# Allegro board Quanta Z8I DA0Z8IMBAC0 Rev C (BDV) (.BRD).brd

Outline 237.5 x 219.5 mm; copper layers: TOP, SGND, IN1, SVCC, IN2, IN3, SGND1, IN4, SGND2, BOTTOM. Coordinates in mm from the lower left corner of the outline.

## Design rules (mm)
constraint set DEFAULT: min track width 0.114
net group DFP-S4.5W4.5(3.5: nets PCIE_RCOMP PCIE_RCOMP_P
net group W12-T1234B: nets +3V_RTC +3VLCD_CON_R_C
net group W30-T1234B: nets +5V_KB CRT_VCC_R
net group W80-T1234B: nets +VIN_BLIGHT VCCPRIM_1P05
net group W99-T1234B: nets +VCC_CORE +VCCSA
net group DFP-S4(4: nets M_A_CLKN0 M_A_CLKN1 M_A_CLKP0 M_A_CLKP1 M_A_DQSN0 M_A_DQSN1 M_A_DQSN2 M_A_DQSN3 M_A_DQSN4 M_A_DQSN5 M_A_DQSN6 M_A_DQSN7 M_A_DQSP0 M_A_DQSP1 M_A_DQSP2 M_A_DQSP3 M_A_DQSP4 M_A_DQSP5 M_A_DQSP6 M_A_DQSP7 M_B_CLKN0 M_B_CLKN1 M_B_CLKP0 M_B_CLKP1 M_B_DQSN0 M_B_DQSN1 M_B_DQSN2 M_B_DQSN3 M_B_DQSN4 M_B_DQSN5 M_B_DQSN6 M_B_DQSN7 M_B_DQSP0 M_B_DQSP1 M_B_DQSP2 M_B_DQSP3 M_B_DQSP4 M_B_DQSP5 M_B_DQSP6 M_B_DQSP7
net group DFP-S4(4: nets 1-AUXN 1-AUXP 1-ML0N 1-ML0P 1-ML1N 1-ML1P 1-ML2N 1-ML2P 1-ML3N 1-ML3P 1-SSRXN 1-SSRXP 1-SSTXN 1-SSTXP 1-TX1N 1-TX1P 1-TX2N 1-TX2P C_IN_CLK#_R C_IN_CLK_R C_TX0_HDMI+_R C_TX0_HDMI-_R C_TX1_HDMI+_R C_TX1_HDMI-_R C_TX2_HDMI+_R C_TX2_HDMI-_R CK_XDP_N CK_XDP_P CLK_PCIE_LANN CLK_PCIE_LANP CLK_PCIE_SSDN CLK_PCIE_SSDN_C CLK_PCIE_SSDP CLK_PCIE_SSDP_C CLK_PCIE_WLANN CLK_PCIE_WLANP CLK_VGA_N CLK_VGA_P CNV_WR_CLK_DN CNV_WR_CLK_DP CNV_WR_LANE0_DN CNV_WR_LANE0_DP CNV_WR_LANE1_DN CNV_WR_LANE1_DP CNV_WT_CLK_DN CNV_WT_CLK_DP CNV_WT_LANE0_DN CNV_WT_LANE0_DP CNV_WT_LANE1_DN CNV_WT_LANE1_DP DDI2_AUXN DDI2_AUXP DDI2_TXN0 DDI2_TXN1 DDI2_TXN2 DDI2_TXN3 DDI2_TXP0 DDI2_TXP1 DDI2_TXP2 DDI2_TXP3 DP_AUXN DP_AUXP DP_D0N DP_D0P DP_D1N DP_D1P HDMI_IN_CLK HDMI_IN_CLK# HDMI_IN_D0 HDMI_IN_D0# HDMI_IN_D1 HDMI_IN_D1# HDMI_IN_D2 HDMI_IN_D2# IN_AUX IN_AUX# IN_AUXN IN_AUXP IN_D0N IN_D0P IN_D1N IN_D1P IN_D2N IN_D2P IN_D3N IN_D3P INT_EDP_AUXN INT_EDP_AUXN_C INT_EDP_AUXP INT_EDP_AUXP_C INT_EDP_TXN0 INT_EDP_TXN0_C INT_EDP_TXN1 INT_EDP_TXN1_C INT_EDP_TXP0 INT_EDP_TXP0_C INT_EDP_TXP1 INT_EDP_TXP1_C PCIE_RXN9_LAN PCIE_RXN10_WLAN PCIE_RXN13_SSD PCIE_RXN13_SSD_C PCIE_RXN14_SSD PCIE_RXN14_SSD_C PCIE_RXN15_SSD PCIE_RXN15_SSD_C PCIE_RXN16_SSD PCIE_RXN16_SSD_C PCIE_RXN_LAN_L PCIE_RXP9_LAN PCIE_RXP10_WLAN PCIE_RXP13_SSD PCIE_RXP13_SSD_C PCIE_RXP14_SSD PCIE_RXP14_SSD_C PCIE_RXP15_SSD PCIE_RXP15_SSD_C PCIE_RXP16_SSD PCIE_RXP16_SSD_C PCIE_RXP_LAN_L PCIE_TXN9_LAN PCIE_TXN9_LAN_C PCIE_TXN10_WLAN PCIE_TXN10_WLAN_C PCIE_TXN13_SSD PCIE_TXN13_SSD_C PCIE_TXN14_SSD PCIE_TXN14_SSD_C PCIE_TXN15_SSD PCIE_TXN15_SSD_C PCIE_TXN16_SSD PCIE_TXN16_SSD_C PCIE_TXP9_LAN PCIE_TXP9_LAN_C PCIE_TXP10_WLAN PCIE_TXP10_WLAN_C PCIE_TXP13_SSD PCIE_TXP13_SSD_C PCIE_TXP14_SSD PCIE_TXP14_SSD_C PCIE_TXP15_SSD PCIE_TXP15_SSD_C PCIE_TXP16_SSD PCIE_TXP16_SSD_C PEG_RXN5 PEG_RXN5_C PEG_RXN6 PEG_RXN6_C PEG_RXN7 PEG_RXN7_C PEG_RXN8 PEG_RXN8_C PEG_RXP5 PEG_RXP5_C PEG_RXP6 PEG_RXP6_C PEG_RXP7 PEG_RXP7_C PEG_RXP8 PEG_RXP8_C PEG_TXN5 PEG_TXN5_C PEG_TXN6 PEG_TXN6_C PEG_TXN7 PEG_TXN7_C PEG_TXN8 PEG_TXN8_C PEG_TXP5 PEG_TXP5_C PEG_TXP6 PEG_TXP6_C PEG_TXP7 PEG_TXP7_C PEG_TXP8 PEG_TXP8_C SATA_RXN0_CN SATA_RXN0_HDD SATA_RXN0_IN SATA_RXN_OUT SATA_RXP0_CN SATA_RXP0_HDD SATA_RXP0_IN SATA_RXP_OUT SATA_TXN0_CN SATA_TXN0_HDD SATA_TXN0_IN SATA_TXN_OUT SATA_TXP0_CN SATA_TXP0_HDD SATA_TXP0_IN SATA_TXP_OUT TYPEC1_RX1N TYPEC1_RX1P TYPEC1_RX2N TYPEC1_RX2P TYPEC1_TX1N TYPEC1_TX1P TYPEC1_TX2N TYPEC1_TX2P USB30_RX1+ USB30_RX1+_C USB30_RX1- USB30_RX1-_C USB30_RX2+ USB30_RX2+_C USB30_RX2- USB30_RX2-_C USB30_RX3+ USB30_RX3- USB30_RX4+ USB30_RX4- USB30_TX1+ USB30_TX1+_C USB30_TX1+_C_R USB30_TX1- USB30_TX1-_C USB30_TX1-_C_R USB30_TX2+ USB30_TX2+_C USB30_TX2+_C_R USB30_TX2- USB30_TX2-_C USB30_TX2-_C_R USB30_TX3+ USB30_TX3- USB30_TX4+ USB30_TX4- USBP1+ USBP1+_R USBP1- USBP1-_R USBP2+ USBP2+_C USBP2+_C_R USBP2- USBP2-_C USBP2-_C_R USBP3+_TPC USBP3-_TPC USBP4+_DB USBP4+_DB_USB USBP4-_DB USBP4-_DB_USB USBP5+_CAM USBP5+_CAM_C USBP5-_CAM USBP5-_CAM_C USBP6+_CR USBP6-_CR USBP7+_FP USBP7+_FP_P4 USBP7-_FP USBP7-_FP_P4 USBP8+_LTE USBP8-_LTE USBP9+_HUB USBP9+_TS USBP9-_HUB USBP9-_TS USBP10+_BT USBP10+_R USBP10-_BT USBP10-_R USBP_TYPC+_C USBP_TYPC-_C VGA_DDI2_AUXN_C VGA_DDI2_AUXP_C VGA_DDI2_TXN0_C VGA_DDI2_TXN1_C VGA_DDI2_TXP0_C VGA_DDI2_TXP1_C
net group DFP-S4.5(4.5: nets PEX_TSTCLK PEX_TSTCLK# VMA_CLK0 VMA_CLK0# VMA_CLK1 VMA_CLK1# VMA_WCK01 VMA_WCK01# VMA_WCK23 VMA_WCK23# VMA_WCK45 VMA_WCK45# VMA_WCK67 VMA_WCK67#
net group DFP-S7(9: nets MDI0+ MDI0+_1 MDI0- MDI0-_1 MDI1+ MDI1+_1 MDI1- MDI1-_1 MDI2+ MDI2+_1 MDI2- MDI2-_1 MDI3+ MDI3+_1 MDI3- MDI3-_1
net group DFP-S7(9: nets C_IN_CLK C_IN_CLK# C_TX0_HDMI+ C_TX0_HDMI- C_TX1_HDMI+ C_TX1_HDMI- C_TX2_HDMI+ C_TX2_HDMI- INT_HDMICLK+_OUT INT_HDMICLK-_OUT INT_HDMITX0N_OUT INT_HDMITX0P_OUT INT_HDMITX1N_OUT INT_HDMITX1P_OUT INT_HDMITX2N_OUT INT_HDMITX2P_OUT TMDS_CLK+ TMDS_CLK- TMDS_D0+ TMDS_D0- TMDS_D1+ TMDS_D1- TMDS_D2+ TMDS_D2-
net group GND: nets GND
net group W4-T134B: nets CFG_RCOMP CNV_WT_RCOMP EDRAM_OPIO_RCOMP EMMC_RCOMP EOPIO_RCOMP PCH_OPI_RCOMP PROC_POPIRCOMP SD_1P8_RCOPM USB2_COMP
net group W4-T1234B: nets 5V_HSMBCK 5V_HSMBDT +1.2VSUS CNV_BRI_DT CNV_BRI_DT_R CNV_BRI_RSP CNV_BRI_RSP_L CNV_RGI_DT CNV_RGI_DT_R CNV_RGI_RSP CNV_RGI_RSP_L HDMI_HPD HDMI_HPD_C HDMI_HPD_CON HDMI_MB_HPD_R HDMI_SCLK HDMI_SDATA N17061319 PULSAR_38P4M_REFCLK PULSAR_38P4M_REFCLK_R SDVO_CLK SDVO_DATA TYPEC_DDI2_HPD
net group W4.5(3.5: nets DDR4_DRAMRST# DRAM_RESET# M_A_DQ0 M_A_DQ1 M_A_DQ2 M_A_DQ3 M_A_DQ4 M_A_DQ5 M_A_DQ6 M_A_DQ7 M_A_DQ8 M_A_DQ9 M_A_DQ10 M_A_DQ11 M_A_DQ12 M_A_DQ13 M_A_DQ14 M_A_DQ15 M_A_DQ16 M_A_DQ17 M_A_DQ18 M_A_DQ19 M_A_DQ20 M_A_DQ21 M_A_DQ22 M_A_DQ23 M_A_DQ24 M_A_DQ25 M_A_DQ26 M_A_DQ27 M_A_DQ28 M_A_DQ29 M_A_DQ30 M_A_DQ31 M_A_DQ32 M_A_DQ33 M_A_DQ34 M_A_DQ35 M_A_DQ36 M_A_DQ37 M_A_DQ38 M_A_DQ39 M_A_DQ40 M_A_DQ41 M_A_DQ42 M_A_DQ43 M_A_DQ44 M_A_DQ45 M_A_DQ46 M_A_DQ47 M_A_DQ48 M_A_DQ49 M_A_DQ50 M_A_DQ51 M_A_DQ52 M_A_DQ53 M_A_DQ54 M_A_DQ55 M_A_DQ56 M_A_DQ57 M_A_DQ58 M_A_DQ59 M_A_DQ60 M_A_DQ61 M_A_DQ62 M_A_DQ63 M_B_DQ0 M_B_DQ1 M_B_DQ2 M_B_DQ3 M_B_DQ4 M_B_DQ5 M_B_DQ6 M_B_DQ7 M_B_DQ8 M_B_DQ9 M_B_DQ10 M_B_DQ11 M_B_DQ12 M_B_DQ13 M_B_DQ14 M_B_DQ15 M_B_DQ16 M_B_DQ17 M_B_DQ18 M_B_DQ19 M_B_DQ20 M_B_DQ21 M_B_DQ22 M_B_DQ23 M_B_DQ24 M_B_DQ25 M_B_DQ26 M_B_DQ27 M_B_DQ28 M_B_DQ29 M_B_DQ30 M_B_DQ31 M_B_DQ32 M_B_DQ33 M_B_DQ34 M_B_DQ35 M_B_DQ36 M_B_DQ37 M_B_DQ38 M_B_DQ39 M_B_DQ40 M_B_DQ41 M_B_DQ42 M_B_DQ43 M_B_DQ44 M_B_DQ45 M_B_DQ46 M_B_DQ47 M_B_DQ48 M_B_DQ49 M_B_DQ50 M_B_DQ51 M_B_DQ52 M_B_DQ53 M_B_DQ54 M_B_DQ55 M_B_DQ56 M_B_DQ57 M_B_DQ58 M_B_DQ59 M_B_DQ60 M_B_DQ61 M_B_DQ62 M_B_DQ63
net group W4.5(3.5: nets 3602_VRHOT ACZ_BCLK ACZ_RST# ACZ_SDIN0 ACZ_SDOUT ACZ_SYNC BIOS_WP# DMIC_CLK DMIC_CLK_L DMIC_DAT DMIC_DAT_L DNBSWON# EC_PWROK H_PROCHOT# H_VCCST_PWRGD HOLD# HWPG IMVP_PWRGD INTRUDER#_R JTAG_TCK_PCH JTAG_TDI_PCH JTAG_TDO_PCH JTAG_TMS_PCH JTAGX_PCH PCH_AZ_CODEC_BITCLK PCH_AZ_CODEC_RST# PCH_AZ_CODEC_SDIN0 PCH_AZ_CODEC_SDOUT PCH_AZ_CODEC_SYNC PCH_SPI1_CLK PCH_SPI1_CLK_R PCH_SPI1_SI PCH_SPI1_SI_R PCH_SPI1_SO PCH_SPI1_SO_R PCH_SPI_CS0# PCH_SPI_CS0#_R PCH_SPI_IO2 PCH_SPI_IO3 PEGX_RST# PEGX_RST#_C PEX_TERMP PLTRST# PROC_TRST# PROCHOT# PROCHOT_EC PROCPWRGD RSMRST# SD_CDZ SD_CDZ_R SD_CLK SD_CLK_R SD_CMD SD_D0/MS_D6 SD_D1/MS_D7 SD_D2/MS_D5 SD_D3/MS_D4 SD_WP/MS_D1 SIO_RCIN# SPI_TPM_CS# SYS_PWROK SYS_RESET# TESTMODE USB_OC2# VCCST_PWRGD_R VGA_DDC_CLK_RT VGA_DDC_DAT_RT XDP_BPM0 XDP_BPM1 XDP_TCK0 XDP_TDI_CPU XDP_TDO_CPU XDP_TMS_CPU XDP_TRST#_CPU
net group W4.5(3.5: nets 2ND_MBCLK 2ND_MBDATA 27M_XTAL_IN 27M_XTAL_OUT 3602_ALERT# 3602_CLK 3602_VDIO BRIGHT CCG_I2C_SCL CCG_I2C_SCL_D CCG_I2C_SDA CCG_I2C_SDA_D CLK_24M_DEBUG CLK_24M_DEBUG_R CLK_PCI_EC CLK_PCI_EC_R CLK_PCI_LPC_R COMP_CORE COMP_GT COMP_SA DISP_ON DP_HPD EC_PECI EC_PECR_R FB_SA GPUT_CLK_L GPUT_DATA_L H_CPU_SVIDALRT# H_CPU_SVIDCLK H_CPU_SVIDDAT H_CPU_SVIDDAT_R I219_PCH_SMCLK I219_PCH_SMDATA LAD0_R LFRAME#_R LPC_LAD0 LPC_LAD1 LPC_LAD2 LPC_LAD3 LPC_LFRAME# PCH_BLON_C PCH_DISP_ON PCH_DPST_PWM PCH_LVDS_BLON PCIE_CLKREQ_LAN# PCIE_CLKREQ_SSD# PCIE_CLKREQ_VGA# PCIE_CLKREQ_WLAN# PWM-VID RGND_CORE RGND_GT RGND_SA RTC_RST# RTC_X1 RTC_X2 SMB_ME1_CLK SMB_ME1_DAT SMB_PCH_CLK SMB_PCH_DAT SMB_RUN_CLK SMB_RUN_DAT SRTC_RST# SUSCLK_32K SUSCLK_32KHZ SYS_SHDN# THERMTRIP# THERMTRIP#_CPU TP_I2C_CLK TP_I2C_DATA TP_SMB_CLK TP_SMB_DATA TS_I2C_SCL TS_I2C_SCL_C TS_I2C_SDA TS_I2C_SDA_C ULT_EDP_HPD ULT_EDP_HPD_R VCCGT_SENSE VCORE_SENSE VCORESS_SENSE VGA_VCCSENSE VGA_VSSSENSE VR_SVID_ALERT#_VCORE VR_SVID_CLK_R VSEN_CORE VSEN_GT VSEN_SA VSSGT_SENSE XCLK_BIASREF XTAL24_IN XTAL24_OUT
net group W4.5-TB: nets CRT_B CRT_B1 CRT_G CRT_G1 CRT_R CRT_R1 CRTHSYNC CRTHSYNC_R CRTVSYNC CRTVSYNC_R
net group W5-T134B: nets EDP_RCOMP
net group W5.5(4: nets M_A_A0 M_A_A1 M_A_A2 M_A_A3 M_A_A4 M_A_A5 M_A_A6 M_A_A7 M_A_A8 M_A_A9 M_A_A10 M_A_A11 M_A_A12 M_A_A13 M_A_ACT# M_A_ALERT# M_A_BG#0 M_A_BG#1 M_A_BS#0 M_A_BS#1 M_A_CAS# M_A_CKE0 M_A_CKE1 M_A_CS#0 M_A_CS#1 M_A_DIM0_ODT0 M_A_DIM0_ODT1 M_A_PARITY M_A_RAS# M_A_WE# M_B_A0 M_B_A1 M_B_A2 M_B_A3 M_B_A4 M_B_A5 M_B_A6 M_B_A7 M_B_A8 M_B_A9 M_B_A10 M_B_A11 M_B_A12 M_B_A13 M_B_ACT# M_B_ALERT# M_B_BG#0 M_B_BG#1 M_B_BS#0 M_B_BS#1 M_B_CAS# M_B_CKE0 M_B_CKE1 M_B_CS#0 M_B_CS#1 M_B_DIM0_ODT0 M_B_DIM0_ODT1 M_B_PARITY M_B_RAS# M_B_WE#
net group W6-T134B: nets TYPEC1_CCG1_CC2
net group W6-T1234B: nets +3VPCU_EC
net group W7(5: nets FBA_CMD0 FBA_CMD1 FBA_CMD2 FBA_CMD3 FBA_CMD4 FBA_CMD5 FBA_CMD6 FBA_CMD7 FBA_CMD8 FBA_CMD9 FBA_CMD10 FBA_CMD11 FBA_CMD12 FBA_CMD13 FBA_CMD14 FBA_CMD15 FBA_CMD16 FBA_CMD17 FBA_CMD18 FBA_CMD19 FBA_CMD20 FBA_CMD21 FBA_CMD22 FBA_CMD23 FBA_CMD24 FBA_CMD25 FBA_CMD26 FBA_CMD27 FBA_CMD28 FBA_CMD29 FBA_CMD30 FBA_CMD31 FBA_DBI0 FBA_DBI1 FBA_DBI2 FBA_DBI3 FBA_DBI4 FBA_DBI5 FBA_DBI6 FBA_DBI7 FBA_EDC0 FBA_EDC1 FBA_EDC2 FBA_EDC3 FBA_EDC4 FBA_EDC5 FBA_EDC6 FBA_EDC7 VMA_DQ0 VMA_DQ1 VMA_DQ2 VMA_DQ3 VMA_DQ4 VMA_DQ5 VMA_DQ6 VMA_DQ7 VMA_DQ8 VMA_DQ9 VMA_DQ10 VMA_DQ11 VMA_DQ12 VMA_DQ13 VMA_DQ14 VMA_DQ15 VMA_DQ16 VMA_DQ17 VMA_DQ18 VMA_DQ19 VMA_DQ20 VMA_DQ21 VMA_DQ22 VMA_DQ23 VMA_DQ24 VMA_DQ25 VMA_DQ26 VMA_DQ27 VMA_DQ28 VMA_DQ29 VMA_DQ30 VMA_DQ31 VMA_DQ32 VMA_DQ33 VMA_DQ34 VMA_DQ35 VMA_DQ36 VMA_DQ37 VMA_DQ38 VMA_DQ39 VMA_DQ40 VMA_DQ41 VMA_DQ42 VMA_DQ43 VMA_DQ44 VMA_DQ45 VMA_DQ46 VMA_DQ47 VMA_DQ48 VMA_DQ49 VMA_DQ50 VMA_DQ51 VMA_DQ52 VMA_DQ53 VMA_DQ54 VMA_DQ55 VMA_DQ56 VMA_DQ57 VMA_DQ58 VMA_DQ59 VMA_DQ60 VMA_DQ61 VMA_DQ62 VMA_DQ63
net group W7-T1234B: nets +3.3V_TYPEC_MUX1
net group W8-T1234B: nets +1.05V_LAN +1V8_AON +3V +3V3_TPM +3V_DEEP_SUS +3V_LAN +3V_LDO_EC +3V_S5 +3V_WLAN_P +3VSPI +5V_PVDD +5VA +5VPCU +A3VPCU +AZA_VDD +G_SEN_PW +USBPWR0 +USBPWR1 +VCCIO +VCCST +VIN AVDD2 DVDD_IO RSET VCCDSW_1P05 VCCPRIM_1P8
net group W10-T134B: nets +SMDDR_VREF_DQ1_M1
net group W10-T1234B: nets +1.05V_DEEP_SUS +1.8V_DEEP_SUS +1.8V_S5 +1V8_GFX_MAIN +3V_EC +3VPCU_ECPLL +PBA_PWR_C +VDDQ_VTT +VGPU_CORE DCPRTC NV_PLLVDD SP_PLLVDD TYPEC1_USB0 VCCA_19P2_1P05 VCCA_OC_1P05 VCCA_SRC_1P05 VCCA_XTAL_1P05 VCCDSW_3P32
net group W12-TB: nets RREF
net group W13-T1234B: nets +1.35V_GFX
net group W14-T1234B: nets +2.5V_SUS
net group W15-T134B: nets SM_RCOMP_0 SM_RCOMP_1 SM_RCOMP_2 TYPEC1_CCG1_CC1
net group W15-T1234B: nets +1.03_GFX +3V_SSD +VCCLDOSRAM_1P24 FB_CAL_PD_VDDQ HP-L2 HP-L3 HP-R2 HP-R3 HP_JD# LINE1-L LINE1-R LINE1-VREFO-L LINE1-VREFO-R MIC2-VREFO SENSEA VCCPRIM_3P3
net group W20-T134B: nets +SMDDR_VREF_DIMM FBA_VREFC_1 FBA_VREFC_2 SM_VREF SMDDR_VREF_DQ1_M3
net group W20-T1234B: nets +3V_RTC_0 +3V_RTC_1 +3V_RTC_2 +5V_FAN +5V_HDMIC +601_VCC +CRT_VDDA33 +PBA_PWR +PBA_PWR_R +VCCPLL +VCCPLL_OC +VCCRTC +VCCSTG +VDDQ FB_CAL_TERM_GND VCCAPLL_1.05V VCCDPHY_1P24 VCCDSW_GPIO VCCDUSB_1P05 VCCHDA VCCSPI
net group W40-T1234B: nets +3VLCD_CON +3VLCD_CON_R L_SPK+ L_SPK+_1 L_SPK- L_SPK-_1 R_SPK+ R_SPK+_1 R_SPK- R_SPK-_1 RING2 SLEEVE VCCMPHYGTAON_1P05
net group W60-T1234B: nets +1.05V_LAN_REGOUT

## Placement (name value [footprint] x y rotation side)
C1  0.033u/16V_4  [C0402]  117.55 122.86 0 top
C2  *0.033u/16V_4  [C0402]  117.55 123.82 180 top
C3  *0.1U/16V_2  [C0201]  77.46 128.75 0 top
C5  *0.47u/6.3V_2  [C0201]  90.62 107.46 90 top
C6  *0.47u/6.3V_2  [C0201]  107.21 132.99 90 top
C7  *0.1u/16V_2  [C0201]  118.08 115.95 90 bottom
C8  0.01u/50V_4  [C0402]  83.8 126.05 0 top
C11  *10U/6.3V_4  [C0402]  110.32 141.94 90 top
C12  10u/6.3V_4  [C0402]  109.36 141.94 90 top
C13  *22U/6.3V_6  [C0603]  132.79 154.28 270 top
C14  10u/6.3V_4  [C0402]  109.26 139.95 270 top
C15  22U/6.3V_6  [C0603]  127.67 148.98 90 bottom
C16  1u/6.3V_2  [C0201]  119.25 143.12 90 top
C17  1u/6.3V_2  [C0201]  118.92 144.12 90 top
C18  1u/6.3V_2  [C0201]  117.83 139.85 180 top
C19  22U/6.3V_6  [C0603]  130.33 150.67 90 bottom
C20  10u/6.3V_4  [C0402]  111.28 141.94 90 top
C21  22U/6.3V_6  [C0603]  113.76 144.37 90 top
C22  1u/6.3V_2  [C0201]  116.02 145.59 0 top
C23  1u/6.3V_2  [C0201]  115.92 144.25 270 top
C24  1u/6.3V_2  [C0201]  107.38 141.39 90 top
C25  1u/6.3V_2  [C0201]  120.14 144.85 90 top
C26  22U/6.3V_6  [C0603]  129.51 154.22 270 bottom
C27  *22U/6.3V_6  [C0603]  138.07 144.45 0 bottom
C28  22U/6.3V_6  [C0603]  130.94 154.15 270 bottom
C29  *330u/2.5V_3528H1.9  [C3528]  138.57 150.85 180 bottom
C30  10u/6.3V_4  [C0402]  110.22 139.95 270 top
C31  10u/6.3V_4  [C0402_2]  107.38 143.11 90 top
C32  1u/6.3V_2  [C0201]  115.95 140.71 270 top
C33  1u/6.3V_2  [C0201]  114.99 140.7 270 top
C34  1u/6.3V_2  [C0201]  115.95 142.44 90 top
C35  1u/6.3V_2  [C0201]  114.83 138.98 90 top
C36  1u/6.3V_2  [C0201]  119.07 141.68 90 top
C37  1u/6.3V_2  [C0201]  120.5 143.4 270 top
C38  1u/6.3V_2  [C0201]  114.96 144.25 270 top
C39  1u/6.3V_2  [C0201]  114.99 142.44 90 top
C40  10u/6.3V_4  [C0402]  115.8 138.98 270 top
C41  10u/6.3V_4  [C0402_2]  107.38 144.83 270 top
C42  10u/6.3V_4  [C0402_2]  112.39 141.96 90 top
C43  10u/6.3V_4  [C0402_2]  112.49 139.95 270 top
C44  *22U/6.3V_6  [C0603]  135.64 154.28 270 top
C45  10u/6.3V_4  [C0402_2]  111.3 139.95 270 top
C46  *22U/6.3V_6  [C0603]  134.21 154.28 270 top
C47  0.1u/16V_2  [C0201]  107.38 139.67 90 top
C48  *22U/6.3V_6  [C0603]  109.45 144.38 90 top
C49  *22U/6.3V_6  [C0603]  110.88 144.38 90 top
C50  *22U/6.3V_6  [C0603]  137.95 141.14 0 top
C51  *22U/6.3V_6  [C0603]  138.02 139.72 0 top
C52  *22U/6.3V_6  [C0603]  112.32 144.37 90 top
C53  *22U/6.3V_6  [C0603]  113.79 141.73 270 top
C54  *22U/6.3V_6  [C0603]  138.02 138.29 0 top
C55  22U/6.3V_6  [C0603]  132.23 139.24 270 bottom
C56  10u/6.3V_4  [C0402_2]  133.43 133.7 90 top
C57  47U/6.3V_6  [C0603]  132.11 128.79 180 top
C58  47U/6.3VS_6  [C0603]  133.78 139.24 270 bottom
C59  47U/6.3VS_6  [C0603]  135.27 139.3 270 bottom
C60  *47U/6.3VS_6  [C0603]  136.8 139.3 270 bottom
C61  47U/6.3VS_6  [C0603]  133.22 150.85 90 bottom
C62  47U/6.3VS_6  [C0603]  131.77 150.85 90 bottom
C63  47U/6.3VS_6  [C0603]  133.78 154.22 270 bottom
C64  47U/6.3VS_6  [C0603]  132.36 154.22 270 bottom
C65  47U/6.3VS_6  [C0603]  134.65 150.57 90 bottom
C66  10u/6.3V_4  [C0402_2]  141.68 146.4 0 top
C67  10u/6.3V_4  [C0402_2]  141.66 149.21 0 top
C68  *22U/6.3V_6  [C0603]  137.49 146.63 90 bottom
C69  10u/6.3V_4  [C0402_2]  129 149.49 270 bottom
C70  10u/6.3V_4  [C0402_2]  127.75 152.66 180 bottom
C71  10u/6.3V_4  [C0402_2]  141.68 147.67 0 top
C72  10u/6.3V_4  [C0402_2]  127.92 154.16 90 bottom
C73  *22U/6.3V_6  [C0603]  128.3 151.1 0 bottom
C74  10u/6.3V_4  [C0402]  88.43 164.54 0 top
C75  1u/6.3V_2  [C0201]  55.32 162.64 90 top
C76  1u/6.3V_2  [C0201]  102.9 152.95 90 top
C77  10u/6.3V_4  [C0402]  102.9 140.25 270 top
C78  1u/6.3V_2  [C0201]  108.58 148.26 270 top
C79  1u/6.3V_2  [C0201]  107.47 138.25 180 top
C80  1u/6.3V_2  [C0201]  112.42 135.05 270 top
C81  10u/6.3V_4  [C0402_2]  107.24 148.31 90 top
C82  10u/6.3V_4  [C0402_2]  108.63 146.55 270 top
C83  10u/6.3V_4  [C0402_2]  107.23 146.59 270 top
C84  1u/6.3V_2  [C0201]  132.4 127.09 270 top
C85  1u/6.3V_2  [C0201]  133.12 127.09 270 top
C86  1u/6.3V_2  [C0201]  107.54 136.9 270 top
C87  1u/6.3V_2  [C0201]  102.79 142.49 90 top
C88  1u/6.3V_2  [C0201]  63.31 158.67 0 top
C89  1u/6.3V_2  [C0201]  128.98 125.67 90 top
C90  10u/6.3V_4  [C0402]  48.6 145.87 0 top
C91  10u/6.3V_4  [C0402]  47.69 149.9 90 top
C92  10u/6.3V_4  [C0402]  88.42 166.53 0 top
C93  10u/6.3V_4  [C0402]  81.3 143.05 270 top
C94  *10U/6.3V_4  [C0402]  88.43 165.56 0 top
C95  1u/6.3V_2  [C0201]  102.9 138.2 90 top
C96  1u/6.3V_2  [C0201]  133.2 138.45 270 top
C97  1u/6.3V_2  [C0201]  109.29 138.46 270 top
C98  1u/6.3V_2  [C0201]  111.59 136.74 90 top
C99  1u/6.3V_2  [C0201]  135.56 135.43 90 top
C100  1u/6.3V_2  [C0201]  113.51 136.74 90 top
C101  1u/6.3V_2  [C0201]  110.25 138.46 270 top
C102  1u/6.3V_2  [C0201]  112.55 136.74 90 top
C103  10u/6.3V_4  [C0402_2]  113.82 138.23 90 top
C104  10u/6.3V_4  [C0402]  134.05 138.22 90 top
C105  10u/6.3V_4  [C0402_2]  111.44 138.2 90 top
C106  10u/6.3V_4  [C0402]  110.32 136.74 270 top
C107  10u/6.3V_4  [C0402_2]  112.62 138.2 90 top
C108  10u/6.3V_4  [C0402]  132.67 135.68 270 top
C109  10u/6.3V_4  [C0402]  109.36 136.74 270 top
C110  10u/6.3V_4  [C0402]  135.02 138.22 90 top
C111  10u/6.3V_4  [C0402]  133.7 135.66 270 top
C112  10u/6.3V_4  [C0402]  134.72 135.43 270 top
C113  10u/6.3V_4  [C0402]  131.67 135.43 270 top
C114  10u/6.3V_4  [C0402_2]  136.71 135.35 270 top
C115  10u/6.3V_4  [C0402_2]  136.11 138.22 90 top
C116  1u/6.3V_2  [C0201]  126.67 139.04 180 bottom
C117  1u/6.3V_2  [C0201]  91.06 139.73 0 top
C118  1u/6.3V_2  [C0201]  132.47 133.83 90 top
C119  22U/6.3V_6  [C0603]  134.75 133.24 270 top
C122  1u/6.3V_2  [C0201]  131.75 134.06 270 top
C123  1u/6.3V_2  [C0201]  126.76 131.9 90 top
C124  10u/6.3V_4  [C0402]  44 141.02 270 top
C125  10u/6.3V_4  [C0402]  83.19 142.9 90 top
C126  10u/6.3V_4  [C0402]  84.2 142.9 90 top
C127  10u/6.3V_4  [C0402]  63.03 125.05 0 top
C128  10u/6.3V_4  [C0402]  67.05 135.62 180 top
C129  10u/6.3V_4  [C0402]  65.14 151.27 90 top
C130  1u/6.3V_2  [C0201]  90.56 152.11 180 top
C131  1u/6.3V_2  [C0201]  91.06 155.52 180 top
C132  1u/6.3V_2  [C0201]  91.04 148.45 180 top
C133  1u/6.3V_2  [C0201]  66.13 154.95 270 top
C134  47U/6.3VS_6  [C0603]  124.13 164.84 90 top
C135  10u/6.3V_4  [C0402_2]  107.49 159.1 180 top
C136  10u/6.3V_4  [C0402_2]  134 163.48 270 top
C137  10u/6.3V_4  [C0402_2]  115.98 167.81 180 top
C138  22U/6.3V_6  [C0603]  112.29 174.2 90 bottom
C139  22U/6.3V_6  [C0603]  116.65 173.85 90 bottom
C140  22U/6.3V_6  [C0603]  120.04 168.96 180 top
C141  22U/6.3V_6  [C0603]  117.37 169.21 180 top
C142  10u/6.3V_4  [C0402]  115.62 147.38 270 top
C143  10u/6.3V_4  [C0402]  114.93 152.6 90 top
C144  10u/6.3V_4  [C0402_2]  115.77 150.87 270 top
C145  22U/6.3V_6  [C0603]  119.74 171.24 270 top
C146  22U/6.3V_6  [C0603]  118.11 171.24 270 top
C147  22U/6.3V_6  [C0603]  116.48 171.24 270 top
C148  22U/6.3V_6  [C0603]  115.15 173.87 270 bottom
C149  22U/6.3V_6  [C0603]  118.1 173.4 270 bottom
C150  10u/6.3V_4  [C0402_2]  114.07 169.59 90 top
C151  10u/6.3V_4  [C0402_2]  107.49 157.88 180 top
C152  10u/6.3V_4  [C0402_2]  131.53 163.04 270 top
C153  10u/6.3V_4  [C0402_2]  130.72 164.55 180 top
C154  10u/6.3V_4  [C0402_2]  107.49 156.66 180 top
C155  10u/6.3V_4  [C0402]  107.49 153.56 180 top
C156  10u/6.3V_4  [C0402]  107.49 154.53 180 top
C157  10u/6.3V_4  [C0402_2]  117.72 167.03 270 top
C158  10u/6.3V_4  [C0402]  107.49 155.55 180 top
C159  22U/6.3V_6  [C0603]  113.73 173.87 90 bottom
C160  22U/6.3V_6  [C0603]  110.87 173.94 90 bottom
C161  22U/6.3V_6  [C0603]  121.92 164.31 0 top
C162  10u/6.3V_4  [C0402_2]  119.06 147.98 270 top
C163  10u/6.3V_4  [C0402]  117.7 149.55 90 top
C164  10u/6.3V_4  [C0402]  117.75 147.44 270 top
C165  10u/6.3V_4  [C0402_2]  115.73 149.14 90 top
C166  22U/6.3V_6  [C0603]  112.88 171.37 0 top
C167  22U/6.3V_6  [C0603]  121.16 171.24 90 top
C168  22U/6.3V_6  [C0603]  110.12 171.88 180 bottom
C169  22U/6.3V_6  [C0603]  125.55 164.84 90 top
C170  22U/6.3V_6  [C0603]  110.16 150.24 270 top
C171  22U/6.3V_6  [C0603]  111.58 150.24 270 top
C172  22U/6.3V_6  [C0603]  113 150.24 90 top
C173  22U/6.3V_6  [C0603]  114.42 150.24 90 top
C174  22U/6.3V_6  [C0603]  107.7 150.82 180 top
C175  22U/6.3V_6  [C0603]  107.71 152.35 180 top
C176  22U/6.3V_6  [C0603]  113.74 152.9 270 top
C177  1u/6.3V_2  [C0201]  112.29 169.59 180 bottom
C178  1u/6.3V_2  [C0201]  113.82 170.35 180 bottom
C179  1u/6.3V_2  [C0201]  112.29 170.35 0 bottom
C180  1u/6.3V_2  [C0201]  112.29 168.83 0 bottom
C181  1u/6.3V_2  [C0201]  116.48 170.35 180 bottom
C182  1u/6.3V_2  [C0201]  113.82 169.59 180 bottom
C183  1u/6.3V_2  [C0201]  114.91 169.59 180 bottom
C184  1u/6.3V_2  [C0201]  116.48 168.83 0 bottom
C185  1u/6.3V_2  [C0201]  114.91 170.35 180 bottom
C186  1u/6.3V_2  [C0201]  114.91 168.83 180 bottom
C187  1u/6.3V_2  [C0201]  116.48 169.59 0 bottom
C188  1u/6.3V_2  [C0201]  113.82 168.83 0 bottom
C189  1u/6.3V_2  [C0201]  117.99 109.9 270 bottom
C190  0.1u/16V_2  [C0201]  118.75 109.9 90 bottom
C191  *22p/50V_4  [C0402]  117.96 104.47 90 bottom
C192  0.22u/10V_2  [C0201]  127.36 129.21 0 bottom
C193  0.22u/10V_2  [C0201]  127.36 128.49 0 bottom
C194  0.22u/10V_2  [C0201]  129.82 129.56 0 bottom
C195  0.22u/10V_2  [C0201]  129.82 130.35 0 bottom
C200  0.1u/16V_2  [C0201]  126.14 131.9 0 bottom
C201  0.1u/16V_2  [C0201]  126.14 132.61 0 bottom
C202  0.1u/16V_2  [C0201]  181.28 114.58 180 bottom
C203  0.1u/16V_2  [C0201]  181.28 113.81 180 bottom
C204  *2.2p/50V_4  [C0402]  124.03 121.84 90 top
C205  10P/50V_4  [C0402]  124.66 115.21 180 bottom
C206  15p/50V_4  [C0402]  101.67 117.33 180 bottom
C208  10P/50V_4  [C0402]  126.39 115.21 0 bottom
C209  15p/50V_4  [C0402]  105.16 117.75 0 bottom
C212  *0.1u/16V_2  [C0201]  76.58 95.33 0 top
C213  3p/50V_4  [C0402]  89.77 131.34 180 top
C214  3p/50V_4  [C0402]  86.31 134.08 90 top
C215  3p/50V_4  [C0402]  25.53 31.42 0 bottom
C216  15p/50V_4  [C0402]  80.57 134.03 180 top
C217  15p/50V_4  [C0402]  85.27 134.08 90 top
C218  15p/50V_4  [C0402]  83.56 130.93 0 top
C219  0.1u/16V_2  [C0201]  124.12 123.24 0 top
C220  1u/6.3V_2  [C0201]  110.99 118.16 0 bottom
C221  0.1u/16V_2  [C0201]  110.99 117.45 0 bottom
C222  1u/6.3V_2  [C0201]  125.43 122.32 180 top
C223  1u/6.3V_2  [C0201]  111.05 134.97 270 top
C224  1u/6.3V_2  [C0201]  122.58 117.9 180 top
C225  1u/6.3V_2  [C0201]  108.79 134.97 270 top
C226  1u/6.3V_2  [C0201]  132.32 117.89 180 bottom
C227  1u/6.3V_2  [C0201]  125.25 116.18 270 top
C228  4.7u/6.3V_4  [C0402]  107.8 117.9 0 bottom
C229  1u/6.3V_2  [C0201]  109.42 132.69 180 top
C230  10u/6.3V_4  [C0402]  122.45 117.93 0 bottom
C231  3p/50V_4  [C0402]  127.74 125.65 0 top
C232  3p/50V_4  [C0402]  126.09 128.94 180 top
C233  10u/6.3V_4  [C0402]  128.12 115.08 180 bottom
C234  10u/6.3V_4  [C0402]  128.12 116.05 180 bottom
C235  1u/6.3V_2  [C0201]  125.9 131.7 180 top
C236  1u/6.3V_2  [C0201]  92.68 109.85 0 top
C237  0.1u/6.3V_2  [C0201]  114.21 119.82 0 top
C238  1u/6.3V_2  [C0201]  110.29 134.97 270 top
C239  *0.1u/16V_2  [C0201]  89.38 110.16 90 top
C240  1u/6.3V_2  [C0201]  90.11 110.16 90 top
C241  3p/50V_4  [C0402]  112.68 118.25 90 top
C242  1u/6.3V_2  [C0201]  96.24 105.38 270 bottom
C243  3p/50V_4  [C0402]  113.09 115.09 0 top
C244  1u/6.3V_2  [C0201]  132.31 118.64 0 bottom
C245  47U/6.3V_6  [C0603]  131.8 119.77 0 bottom
C246  0.1u/16V_2  [C0201]  80.67 122.55 90 top
C247  *10P/50V_4  [C0402]  96.27 108.47 90 bottom
C248  *0.1U/16V_2  [C0201]  118.93 101.44 180 bottom
C249  *0.1u/6.3V_2  [C0201]  45.31 145.21 270 top
C250  1u/6.3V_4  [C0402]  52.41 133.39 270 top
C251  1u/6.3V_4  [C0402]  46.15 103.63 90 top
C252  1u/6.3V_4  [C0402]  44.05 138.58 270 top
C253  1u/6.3V_4  [C0402]  48.3 105.79 270 top
C254  1u/6.3V_4  [C0402]  45.45 130.84 180 top
C255  1u/6.3V_4  [C0402]  47.17 103.63 90 top
C256  1u/6.3V_4  [C0402]  54.35 127.77 90 top
C257  1u/6.3V_4  [C0402]  47.28 105.79 270 top
C258  1u/6.3V_4  [C0402]  53.45 133.38 270 top
C259  10u/6.3V_4  [C0402]  45.14 103.63 90 top
C260  1u/6.3V_4  [C0402]  54.55 110.68 180 top
C261  10u/6.3V_4  [C0402]  55.97 107.2 270 top
C262  1u/6.3V_4  [C0402]  46.72 168.54 270 top
C263  1u/6.3V_4  [C0402]  43.98 142.98 270 top
C264  0.1u/6.3V_2  [C0201]  45.98 128.56 0 top
C265  2.2U/10V_4  [C0402]  45.52 127.04 180 top
C266  0.022u/25V_4  [C0402]  44.65 120.01 180 top
C267  10u/6.3V_4  [C0402]  46.96 115.51 0 top
C268  10u/6.3V_4  [C0402]  43.95 133.83 270 top
C269  1u/6.3V_4  [C0402]  51.27 103.11 90 top
C270  10u/6.3V_4  [C0402]  44.04 145.03 270 top
C271  1u/6.3V_4  [C0402]  50.26 103.11 90 top
C272  10u/6.3V_4  [C0402]  58.08 141.84 180 top
C273  10u/6.3V_4  [C0402]  50.77 106.69 270 top
C274  10u/6.3V_4  [C0402]  46.14 158.99 180 top
C275  10u/6.3V_4  [C0402]  49.76 106.69 270 top
C276  10u/6.3V_4  [C0402]  53.95 135.2 0 top
C277  10u/6.3V_4  [C0402]  51.18 142.98 0 top
C278  0.1u/6.3V_2  [C0201]  53.19 106.4 0 top
C279  10u/6.3V_4  [C0402]  44.13 148.68 270 top
C280  2.2U/10V_4  [C0402]  52.18 106.84 270 top
C282  10u/25V_6  [C0603]  12.43 63.51 180 top
C347  EV@22U/6.3VS_4  [C0402]  141.08 210.54 180 bottom
C348  EV@10u/6.3V_4  [C0402]  141.03 209.55 180 bottom
C349  EV@4.7u/6.3V_4  [C0402_2]  143.11 209.51 0 bottom
C350  EV@4.7u/6.3V_4  [C0402_2]  141.02 211.67 180 bottom
C351  EV@1u/6.3V_4  [C0402]  129.57 195.32 270 top
C352  EV@1u/6.3V_4  [C0402]  133.6 195.32 270 top
C353  EV@1u/6.3V_4  [C0402]  135.03 191.51 90 top
C354  EV@1u/6.3V_4  [C0402]  143.07 209.66 180 top
C355  EV@47U/6.3V_6  [C0603]  137.95 210.86 270 bottom
C356  EV@4.7u/6.3V_4  [C0402_2]  140.31 208.21 0 bottom
C357  EV@4.7u/6.3V_4  [C0402_2]  133.65 193.54 90 top
C358  EV@0.22u/10V_4  [C0402]  114.95 201.45 270 top
C359  EV@22u/6.3V_6  [C0603]  131.12 210.33 180 bottom
C360  EV@4.7u/6.3V_4  [C0402_2]  146.15 206.12 0 bottom
C361  0.1u/16V_2  [C0201]  17.93 64.14 270 top
C362  EV@1u/6.3V_4  [C0402]  134.52 198.5 90 top
C363  EV@10u/6.3V_4  [C0402]  143.2 210.65 0 bottom
C364  *EV@0.1u/16V_4  [C0402]  116.76 207.65 270 bottom
C365  EV@1u/6.3V_4  [C0402]  129.57 191.77 270 top
C366  EV@4.7u/6.3V_4  [C0402_2]  136.04 198.24 180 top
C367  EV@4.7u/6.3V_4  [C0402_2]  133.65 191.77 270 top
C368  EV@4.7u/6.3V_4  [C0402_2]  126.14 194.56 270 top
C369  EV@4.7u/6.3V_4  [C0402_2]  131.09 190.24 0 top
C370  EV@0.22u/10V_4  [C0402]  113.98 201.45 270 top
C371  EV@0.1u/16V_4  [C0402]  126.01 188.03 270 top
C372  EV@4.7u/6.3V_4  [C0402_2]  132.87 190.24 180 top
C373  EV@4.7u/6.3V_4  [C0402_2]  127.33 191.77 270 top
C374  EV@4.7u/6.3V_4  [C0402_2]  132.49 195.37 270 top
C375  EV@0.1u/16V_4  [C0402]  128.27 187.96 90 top
C376  EV@4.7u/6.3V_4  [C0402_2]  113.48 181.88 180 top
C377  EV@22U/6.3VS_4  [C0402]  143.79 207.64 90 bottom
C378  EV@1u/6.3V_4  [C0402]  126.97 188.03 270 top
C379  EV@4.7u/6.3V_4  [C0402_2]  146.15 204.85 0 bottom
C380  EV@4.7u/6.3V_4  [C0402_2]  131.09 188.84 0 top
C381  EV@10u/6.3V_4  [C0402]  145.82 207.64 90 bottom
C382  EV@0.22u/10V_4  [C0402]  128.15 208.39 90 top
C383  EV@10u/6.3V_4  [C0402]  144.81 207.64 90 bottom
C384  EV@0.22u/10V_4  [C0402]  127.13 208.39 90 top
C385  EV@220u/2V_7343H1.0  [CC7343]  134.04 215.03 180 bottom
C386  EV@22u/6.3V_6  [C0603]  129.46 188.23 90 top
C387  EV@47U/6.3V_6  [C0603]  131.12 211.86 180 bottom
C388  EV@10u/6.3V_4  [C0402]  134.29 207.67 180 bottom
C389  *EV@10u/6.3V_4  [C0402]  138.4 207.66 180 bottom
C390  0.1u/16V_2  [C0201]  14.02 69.67 0 top
C391  *EV@10u/6.3V_4  [C0402]  136.07 207.67 0 bottom
C392  EV@4.7u/6.3V_4  [C0402_2]  162.91 207.98 180 top
C393  *EV@10u/6.3V_4  [C0402]  131.91 207.67 0 bottom
C394  EV@1u/6.3V_4  [C0402]  114.9 190.94 90 top
C395  EV@1u/6.3V_4  [C0402]  127.3 198.42 90 top
C396  EV@4.7u/6.3V_4  [C0402_2]  131.91 208.81 0 bottom
C397  EV@4.7u/6.3V_4  [C0402_2]  138.4 208.81 180 bottom
C398  EV@0.1u/16V_4  [C0402]  124.62 189.14 180 top
C399  EV@1u/6.3V_4  [C0402]  143.8 208.17 270 top
C400  EV@4.7u/6.3V_4  [C0402_2]  136.07 208.81 0 bottom
C401  EV@0.1u/16V_4  [C0402]  113.91 190.94 90 top
C402  EV@1u/6.3V_4  [C0402]  128.27 198.14 90 top
C403  EV@4.7u/6.3V_4  [C0402_2]  134.29 208.81 180 bottom
C406  EV@4.7u/6.3V_4  [C0402_2]  127.33 189.99 90 top
C407  EV@4.7u/6.3V_4  [C0402_2]  129.06 190.17 180 top
C408  EV@4.7u/6.3V_4  [C0402_2]  127.39 195.67 270 top
C409  EV@4.7u/6.3V_4  [C0402_2]  127.33 193.54 90 top
C410  EV@1u/6.3V_4  [C0402]  132.99 197.15 0 top
C411  EV@1u/6.3V_4  [C0402]  130.66 193.54 90 top
C412  EV@10u/6.3V_4  [C0402]  132.46 191.77 270 top
C413  EV@47U/6.3V_6  [C0603]  108.51 213.38 315 bottom
C414  *EV@47U/6.3V_6  [C0603]  131.66 209.85 270 top
C415  EV@10u/6.3V_4  [C0402]  126.31 196.61 270 top
C416  EV@47U/6.3V_6  [C0603]  106.28 203.01 90 top
C417  *EV@47U/6.3V_6  [C0603]  136.53 210.87 90 bottom
C418  EV@10u/6.3V_4  [C0402]  132.46 193.54 90 top
C419  EV@47U/6.3V_6  [C0603]  130.07 198.62 0 top
C420  *EV@47U/6.3V_6  [C0603]  113.62 207.24 180 bottom
C421  EV@10u/6.3V_4  [C0402]  130.66 191.77 270 top
C422  EV@47U/6.3V_6  [C0603]  113.09 199.84 0 top
C423  *EV@47U/6.3V_6  [C0603]  134.33 209.88 90 top
C424  EV@10u/6.3V_4  [C0402]  130.66 195.32 270 top
C425  EV@0.1u/16V_4  [C0402]  125.35 197.39 270 top
C426  EV@47U/6.3V_6  [C0603]  135.99 209.85 90 top
C427  *EV@47U/6.3V_6  [C0603]  109.53 214.4 135 bottom
C428  EV@10u/6.3V_4  [C0402]  131.09 197.35 0 top
C429  EV@4.7u/6.3V_4  [C0402_2]  124.54 199.24 180 top
C430  EV@10u/6.3V_4  [C0402]  129.57 193.54 90 top
C431  EV@4.7u/6.3V_4  [C0402_2]  124.27 197.31 270 top
C432  EV@10u/6.3V_4  [C0402]  124.87 195.32 90 top
C433  EV@0.1u/16V_4  [C0402]  108.95 183.33 270 bottom
C438  EV@1u/6.3V_4  [C0402]  147.32 182.97 90 top
C439  EV@1u/6.3V_4  [C0402]  135.79 194.2 180 top
C440  EV@1u/6.3V_4  [C0402]  148.67 182.98 90 top
C441  EV@1u/6.3V_4  [C0402]  164.87 194.43 90 top
C442  EV@1u/6.3V_4  [C0402]  161.7 194.43 90 top
C443  EV@10u/6.3V_4  [C0402]  134.9 189.86 180 top
C444  EV@10u/6.3V_4  [C0402]  135.8 193.23 180 top
C445  *EV@22U/6.3V_6  [C0603]  135.43 196.36 180 top
C446  *EV@22U/6.3V_6  [C0603]  146.58 192.15 90 bottom
C447  EV@1u/6.3V_4  [C0402]  134.9 188.84 180 top
C448  EV@10u/6.3V_4  [C0402]  135.79 195.17 180 top
C449  EV@1u/6.3V_4  [C0402]  133.91 187.88 180 top
C450  EV@1u/6.3V_4  [C0402]  132.55 188.59 90 top
C451  EV@22u/6.3V_6  [C0603]  144.93 192.15 90 bottom
C452  EV@0.1u/16V_4  [C0402]  126.38 208.47 270 bottom
C453  EV@22u/6.3V_4  [C0402_2]  135.66 187.7 180 top
C454  EV@0.1u/16V_4  [C0402]  136.39 191.89 0 top
C455  EV@0.1u/16V_4  [C0402]  131.83 186.72 180 top
C456  EV@0.1u/16V_4  [C0402]  114.53 193.79 180 top
C457  EV@0.1u/16V_4  [C0402]  114.92 195.91 90 top
C458  *EV@22u/6.3V_4  [C0402_2]  124.6 190.31 0 top
C459  EV@0.1u/16V_4  [C0402]  125.59 192.75 0 top
C460  EV@0.1u/16V_4  [C0402]  125.59 191.79 0 top
C461  *EV@10u/6.3V_4  [C0402]  114.92 197.64 90 top
C462  *EV@47U/6.3V_6  [C0603]  112.45 197.78 90 top
C463  EV@12p/50V_4  [C0402]  127.41 178.3 180 bottom
C464  EV@12p/50V_4  [C0402]  125.63 178.3 0 bottom
C471  EV@22u/6.3V_6  [C0603]  166.51 192.26 180 top
C472  EV@22u/6.3V_6  [C0603]  162.2 185.16 0 top
C473  EV@22u/6.3V_6  [C0603]  162.69 168.04 90 bottom
C474  EV@22u/6.3V_6  [C0603]  148.49 207.23 0 bottom
C475  EV@22u/6.3V_6  [C0603]  152.3 193.92 0 top
C476  EV@22u/6.3V_6  [C0603]  145.89 185.39 90 bottom
C477  EV@1u/6.3V_4  [C0402]  154.08 195.5 180 top
C478  EV@1u/6.3V_4  [C0402]  164.67 176.48 0 top
C479  EV@1u/6.3V_4  [C0402]  157.57 180.2 270 top
C480  EV@1u/6.3V_4  [C0402]  157.53 202.69 270 top
C481  EV@1u/6.3V_4  [C0402]  160.43 204.59 180 top
C482  EV@1u/6.3V_4  [C0402]  160.17 198.24 90 top
C483  EV@1u/6.3V_4  [C0402]  153.06 176.14 270 top
C484  EV@10u/6.3V_4  [C0402]  164.87 198.5 270 top
C485  *EV@22U/6.3V_6  [C0603]  164.42 200.71 180 top
C486  *EV@22U/6.3V_6  [C0603]  148.49 205.74 0 bottom
C487  EV@22u/6.3V_6  [C0603]  158.45 209.95 270 bottom
C488  EV@22u/6.3V_6  [C0603]  162.2 187.07 0 top
C489  EV@22u/6.3V_6  [C0603]  148.49 204.21 0 bottom
C490  EV@22u/6.3V_6  [C0603]  147.43 185.48 90 bottom
C491  EV@1u/6.3V_4  [C0402]  165.37 182.96 0 top
C492  EV@1u/6.3V_4  [C0402]  156.43 206.05 180 top
C493  EV@1u/6.3V_4  [C0402]  160.17 206.62 180 top
C494  EV@1u/6.3V_4  [C0402]  156.11 181.61 270 top
C495  EV@1u/6.3V_4  [C0402]  155.85 197.86 0 top
C496  EV@1u/6.3V_4  [C0402]  156.24 176.14 90 top
C497  EV@1u/6.3V_4  [C0402]  157.25 169.41 0 bottom
C498  EV@1u/6.3V_4  [C0402]  164.33 201.95 0 top
C499  EV@1u/6.3V_4  [C0402]  155.35 169.41 180 bottom
C500  EV@10u/6.3V_4  [C0402]  162.84 206.88 180 top
C501  EV@10u/6.3V_4  [C0402]  161.95 179.7 0 top
C502  EV@10u/6.3V_4  [C0402]  154.08 180.34 180 top
C503  *EV@22U/6.3V_6  [C0603]  148.96 185.48 90 bottom
C504  *EV@22U/6.3V_6  [C0603]  159.54 169.16 180 bottom
C505  EV@820p/50V_4  [C0402]  159.41 187.45 180 top
C506  EV@820p/50V_4  [C0402]  158.14 192.5 0 top
C508  1u/25V_4  [C0402]  21.79 100.75 180 top
C509  100u/6.3V_12  [C1206]  18.85 98.22 180 bottom
C510  470p/50V_4  [C0402]  22.89 94.38 0 top
C511  0.1u/16V_4  [C0402]  22.89 95.4 0 top
C512  1u/6.3V_4  [C0402]  26.6 97.91 180 bottom
C513  *1.6p/50V_4  [C0402]  21.86 89.67 0 top
C515  470p/50V_4  [C0402]  19.49 88.92 270 bottom
C516  0.1u/16V_4  [C0402]  18.49 88.92 270 bottom
C517  100u/6.3V_12  [C1206]  19.33 90.9 0 bottom
C518  *1.6p/50V_4  [C0402]  21.86 90.82 0 top
C519  0.1u/16V_4  [C0402]  23.55 92.04 0 top
C520  0.1u/16V_4  [C0402]  23.55 93.04 0 top
C521  *1.6p/50V_4  [C0402]  20.06 91.79 0 top
C522  *1.6p/50V_4  [C0402]  20.06 92.93 0 top
C523  *1.6p/50V_4  [C0402]  24.21 105.2 0 top
C524  1u/6.3V_4  [C0402]  220.33 110.44 180 bottom
C526  *1.6p/50V_4  [C0402]  24.21 106.35 0 top
C527  470p/50V_4  [C0402]  217.68 104.67 180 bottom
C528  0.1u/16V_4  [C0402]  220.53 104.67 0 bottom
C529  *100u/6.3V_12  [C1206]  220.27 107.59 90 bottom
C530  0.1u/16V_4  [C0402]  25.63 107.36 0 top
C531  0.1u/16V_4  [C0402]  25.63 108.51 0 top
C532  *1.6p/50V_4  [C0402]  21.82 107.36 0 top
C533  *1.6p/50V_4  [C0402]  21.82 108.51 0 top
C536  0.1u/25V_2  [C0201]  74.86 190.14 180 bottom
C537  0.01u/50V_4  [C0402]  74.86 191.16 0 bottom
C542  4.7u/25V_6  [C0603]  77.4 189.13 0 bottom
C543  0.1u/16V_4  [C0402]  72.44 192.81 180 top
C544  100p/50V_4  [C0402]  73.74 190.84 90 top
C545  *22U/6.3V_6  [C0603]  71.5 190.34 270 top
C546  0.1u/16V_4  [C0402]  70.41 189.38 180 bottom
C547  10P/50V_4  [C0402]  52.89 190.78 90 bottom
C548  10P/50V_4  [C0402]  53.22 192.53 0 bottom
C550  0.1u/16V_4  [C0402]  72.09 187.48 90 top
C551  HDMI_CRT_P2@4.7u/6.3V_6  [C0603]  25.24 157.91 0 top
C552  0.1u/16V_4  [C0402]  65.84 190.78 90 bottom
C553  0.1u/16V_4  [C0402]  64.82 190.78 90 bottom
C554  0.1u/16V_4  [C0402]  63.81 190.78 90 bottom
C555  0.1u/16V_4  [C0402]  62.79 190.78 90 bottom
C556  0.1u/16V_4  [C0402]  66.86 190.78 90 bottom
C557  0.1u/16V_4  [C0402]  67.87 190.78 90 bottom
C558  33p/50V_4  [C0402]  68.02 188.49 270 bottom
C559  1u/6.3V_4  [C0402]  71.05 193.95 180 top
C560  0.01u/50V_4  [C0402]  77.78 192.68 180 top
C561  0.1u/16V_4  [C0402]  77.78 190.65 180 top
C562  10u/6.3V_4  [C0402]  77.78 191.67 180 top
C563  2.2u/6.3V_4  [C0402]  13.86 31.12 90 bottom
C564  10u/6.3V_4  [C0402_2]  15.2 27.26 90 top
C565  10u/6.3V_6  [C0603]  26.52 37.66 180 bottom
C566  1u/10V_6  [C0603]  14.69 35.07 270 bottom
C567  1u/10V_6  [C0603]  15.82 39.99 270 bottom
C568  0.1u/16V_4  [C0402]  15.68 27.34 180 bottom
C569  10u/6.3V_4  [C0402_2]  15.72 28.46 180 bottom
C572  10u/6.3V_4  [C0402_2]  17.48 37.11 180 bottom
C573  10u/6.3V_4  [C0402_2]  19.65 26.03 90 bottom
C574  10u/6.3V_4  [C0402_2]  18.23 40.44 0 bottom
C575  0.1u/16V_4  [C0402]  18.23 39.33 0 bottom
C576  10u/6.3V_4  [C0402_2]  22.15 39.39 180 bottom
C577  0.1u/16V_4  [C0402]  22.15 38.25 180 bottom
C578  10u/6.3V_4  [C0402_2]  28.63 31.65 180 bottom
C580  0.1u/16V_4  [C0402]  25.9 35.14 180 bottom
C581  10u/6.3V_4  [C0402_2]  26.12 36.25 180 bottom
C583  33p/50V_4  [C0402]  28.63 35.84 0 bottom
C584  0.1u/16V_4  [C0402]  28.65 28.53 0 bottom
C585  10u/6.3V_4  [C0402_2]  28.25 29.99 90 bottom
C586  *1000p/50V_4  [C0402]  21.88 22.98 180 top
C587  *22p/50V_4  [C0402]  28.63 32.79 0 bottom
C588  *0.1u/16V_4  [C0402]  13.21 14.65 90 top
C589  4.7u/6.3V_6  [C0603]  15.1 23.75 90 bottom
C590  100p/50V_4  [C0402]  6.04 14.75 0 top
C591  100p/50V_4  [C0402]  20.83 26.36 0 top
C592  100p/50V_4  [C0402]  15.27 19.53 0 bottom
C593  100p/50V_4  [C0402]  9.31 28.48 90 bottom
C594  4.7u/6.3V_6  [C0603]  16.57 24.46 90 bottom
C595  *1u/25V_4  [C0402]  33.46 29.99 270 bottom
C596  *0.1u/16V_4  [C0402]  10.58 34.73 270 bottom
C597  *10u/6.3V_6  [C0603]  7.82 31.84 270 bottom
C598  *10u/6.3V_6  [C0603]  12.64 31.52 90 bottom
C599  *0.1u/16V_4  [C0402]  14.99 25.93 90 bottom
C601  SPK_P2@1000p/50V_4  [C0402]  83.57 197.41 180 bottom
C602  SPK_P2@1000p/50V_4  [C0402]  80.83 197.41 0 bottom
C603  SPK_P2@1000p/50V_4  [C0402]  88.07 197.38 180 bottom
C604  SPK_P2@1000p/50V_4  [C0402]  85.3 197.41 0 bottom
C613  *10P/50V_4  [C0402]  14.99 130.19 90 top
C614  *10P/50V_4  [C0402]  15.34 131.55 0 top
C616  220p/50V_4  [C0402]  14.49 133.16 270 bottom
C618  HDMI_R_P4@0.1u/16V_4  [C0402]  18.08 137.09 180 top
C619  HDMI_R_P4@0.1u/16V_4  [C0402]  24.59 137.03 90 top
C628  HDMI_R_P4@0.1u/16V_4  [C0402]  25.74 146.3 90 top
C631  0.1u/16V_4  [C0402]  25.9 168.06 180 top
C632  0.1u/16V_4  [C0402]  25.7 169.71 180 top
C633  0.1u/16V_4  [C0402]  21.38 173.09 0 top
C634  0.1u/16V_4  [C0402]  17.81 173.22 270 top
C635  0.1u/16V_4  [C0402]  15.36 164.18 270 bottom
C636  0.1u/16V_4  [C0402]  16.37 164.18 270 bottom
C638  10p/50V_4  [C0402]  28.88 168.04 180 top
C639  10p/50V_4  [C0402]  28.88 171.09 180 top
C641  0.1u/16V_4  [C0402]  19.3 172.97 0 top
C642  0.1u/16V_4  [C0402]  14.53 167.92 0 top
C645  8111K@0.01u/50V_4  [C0402]  39.04 179.47 90 top
C646  10p/3KV_1808  [CC1808]  28.81 191.11 180 bottom
C669  *HDD_R@47u/6.3V_8  [C0805]  227.89 106.83 180 top
C670  HDD_R@10u/6.3V_4  [C0402_2]  228.27 103.15 90 top
C675  0.1u/25V_4  [C0402]  11.54 69.01 0 top
C676  0.1u/25V_4  [C0402]  11.25 64.75 0 top
C680  *HDD_R@0.1u/16V_4  [C0402]  227.13 103.15 90 top
C689  *HDD_R@0.1u/16V_4  [C0402]  226.11 103.15 90 top
C691  *390p/50V_4  [C0402]  14.59 63.4 0 bottom
C692  *390p/50V_4  [C0402]  11.15 71.83 90 bottom
C695  0.1u/16V_4  [C0402]  133.21 99.22 90 top
C696  10P/50V_4  [C0402]  132.92 96.83 180 top
C697  10P/50V_4  [C0402]  129.45 97.07 0 top
C698  *10P/50V_4  [C0402]  128.81 98.75 0 top
C699  *10P/50V_4  [C0402]  127.07 98.76 180 top
C706  220p/25V_2  [C0201]  177.32 98.83 270 top
C707  220p/25V_2  [C0201]  175.59 98.83 270 top
C708  220p/25V_2  [C0201]  174.12 98.83 270 top
C709  220p/25V_2  [C0201]  178.06 98.83 270 top
C711  220p/25V_2  [C0201]  178.79 98.83 270 top
C713  220p/25V_2  [C0201]  179.53 98.83 270 top
C714  220p/25V_2  [C0201]  180.27 98.83 270 top
C715  220p/25V_2  [C0201]  181.16 98.83 270 top
C716  220p/25V_2  [C0201]  172.24 98.83 270 top
C717  220p/25V_2  [C0201]  172.95 98.83 270 top
C718  220p/25V_2  [C0201]  174.86 98.83 270 top
C719  220p/25V_2  [C0201]  171.53 98.83 270 top
C720  220p/25V_2  [C0201]  189.16 98.83 270 top
C721  220p/25V_2  [C0201]  190.94 98.83 270 top
C722  220p/25V_2  [C0201]  188.27 98.83 270 top
C723  220p/25V_2  [C0201]  187.38 98.83 270 top
C724  220p/25V_2  [C0201]  191.82 98.83 270 top
C725  220p/25V_2  [C0201]  185.6 98.83 270 top
C726  220p/25V_2  [C0201]  190.05 98.83 270 top
C727  220p/25V_2  [C0201]  186.49 98.83 270 top
C728  220p/25V_2  [C0201]  182.05 98.83 270 top
C729  220p/25V_2  [C0201]  182.93 98.83 270 top
C730  220p/25V_2  [C0201]  183.82 98.83 270 top
C731  220p/25V_2  [C0201]  184.71 98.83 270 top
C732  220p/25V_2  [C0201]  170.11 98.88 270 top
C733  220p/25V_2  [C0201]  170.82 98.88 270 top
C734  *2.2u/6.3V_6  [C0603]  213.29 123.72 90 bottom
C735  0.1u/16V_4  [C0402]  210.49 101.11 0 top
C736  4.7u/6.3V_4  [C0402_2]  219 121.31 180 bottom
C737  0.01u/50V_4  [C0402]  219.92 122.75 0 bottom
C740  10u/6.3V_6  [C0603]  91.75 102.74 270 top
C741  0.1u/10V_2  [C0201]  83.24 97.05 180 top
C742  0.1u/10V_2  [C0201]  91.88 100.48 270 top
C743  10u/6.3V_6  [C0603]  92.26 95.04 0 top
C744  0.1u/10V_2  [C0201]  83.24 96.29 180 top
C745  0.1u/10V_2  [C0201]  92.74 97.33 270 top
C749  *2.2u/16V_6  [C0603]  108.46 108.18 270 bottom
C750  *0.01u/50V_4  [C0402]  108.65 111.21 0 bottom
C752  4.7u/6.3V_4  [C0402_2]  101.89 107.75 270 bottom
C753  0.01u/50V_4  [C0402]  103.03 107.75 270 bottom
C770  *10u/6.3V_4  [C0402_2]  221.16 109.5 0 top
C771  10u/6.3V_4  [C0402_2]  221.16 110.77 0 top
C772  0.1u/16V_4  [C0402]  221.16 108.35 0 top
C785  *SSD@0.1u/16V_2  [C0201]  31.18 67.8 90 bottom
C786  SSD@0.1u/16V_2  [C0201]  31.95 67.8 90 bottom
C788  SSD@0.22u/10V_2  [C0201]  32.31 82.95 270 bottom
C789  SSD@0.22u/10V_2  [C0201]  31.55 82.95 270 bottom
C790  SSD@0.22u/10V_2  [C0201]  28.76 82.95 270 bottom
C791  SSD@0.22u/10V_2  [C0201]  27.99 82.95 270 bottom
C792  SSD@0.22u/10V_2  [C0201]  25.21 82.83 270 bottom
C793  SSD@0.22u/10V_2  [C0201]  24.44 82.83 270 bottom
C794  SSD@0.22u/10V_2  [C0201]  21.01 83.08 270 bottom
C795  SSD@0.22u/10V_2  [C0201]  20.25 83.08 270 bottom
C800  *0.1u/16V_2  [C0201]  194.24 122.7 90 bottom
C801  0.01u/10V_2  [C0201]  195 122.7 90 bottom
C802  10u/6.3V_4  [C0402_2]  192.84 103.4 90 bottom
C804  0.1u/16V_2  [C0201]  193.17 123.82 90 bottom
C805  10u/6.3V_4  [C0402_2]  196.31 122.44 0 bottom
C808  HDMI_CRT_P2@2.2u/6.3V_4  [C0402]  29.67 129.81 0 top
C809  HDMI_CRT_P2@0.1u/16V_4  [C0402]  29.52 132.61 90 top
C811  HDMI_CRT_P2@0.1u/16V_4  [C0402]  28.12 132.61 90 top
C812  HDMI_CRT_P2@0.1u/16V_4  [C0402]  27.11 132.61 90 top
C813  HDMI_CRT_P2@0.1u/16V_4  [C0402]  25.71 132.61 90 top
C814  HDMI_CRT_P2@0.1u/16V_4  [C0402]  24.69 132.61 90 top
C815  HDMI_CRT_P2@0.1u/16V_4  [C0402]  23.3 132.61 90 top
C816  HDMI_CRT_P2@0.1u/16V_4  [C0402]  22.28 132.61 90 top
C817  HDMI_CRT_P2@0.1u/16V_4  [C0402]  20.88 132.61 90 top
C841  *0.1u/6.3V_2  [C0201]  147.12 210.59 180 top
C842  0.1u/16V_4  [C0402]  150.97 212.33 270 top
C844  100p/50V_4  [C0402]  26.74 29.38 0 bottom
C845  10u/6.3V_4  [C0402_2]  14.45 37.11 180 bottom
C846  0.1u/16V_4  [C0402]  24.95 29.39 180 bottom
C853  HDMI_R_P4@0.1u/16V_4  [C0402]  23.3 133.39 270 top
C856  *HDMI_CRT_P2@10p/50V_4  [C0402]  18.68 152.7 0 top
C857  *HDMI_CRT_P2@10p/50V_4  [C0402]  18.98 154.72 0 top
C858  *HDMI_CRT_P2@10p/50V_4  [C0402]  19.49 156.47 180 top
C859  HDMI_CRT_P2@10p/50V_4  [C0402]  15.96 156.46 0 top
C860  HDMI_CRT_P2@10p/50V_4  [C0402]  15.84 155.09 90 top
C861  HDMI_CRT_P2@10p/50V_4  [C0402]  15.55 153.06 270 top
C880  HDMI_CRT_P2@0.1u/16V_4  [C0402]  27.56 119.92 90 top
C881  HDMI_CRT_P2@0.1u/16V_4  [C0402]  33.84 130.83 90 top
C882  HDMI_CRT_P2@0.1u/16V_4  [C0402]  31.3 126.21 0 top
C883  HDMI_CRT_P2@0.1u/16V_4  [C0402]  31.3 125.2 0 top
C890  HDMI_CRT_P2@0.1u/16V_4  [C0402]  11.01 159.88 0 bottom
C900  *HDMI_CRT_P2@0.1u/16V_4  [C0402]  13.43 148.87 180 top
C912  HDMI_CRT_P2@0.01u/50V_4  [C0402]  32.05 129.78 90 top
C913  HDMI_CRT_P2@0.01u/50V_4  [C0402]  20.49 130.64 180 top
C1044  *0.1u/25V_6  [C0603]  16.18 157.25 90 bottom
C1189  0.1u/10V_2  [C0201]  149.48 106.12 90 top
C1190  0.1u/10V_2  [C0201]  149.28 105.18 180 top
C1208  180p/50V_4  [C0402]  169.27 104.04 0 top
C1210  180p/50V_4  [C0402]  170.06 102.99 180 top
C1211  1u/6.3V_2  [C0201]  82.86 105.79 180 top
C1214  1u/6.3V_2  [C0201]  78.06 100.5 0 top
C1217  1u/6.3V_2  [C0201]  80.32 103.35 90 top
C1643  5.6p/50V_4  [C0402]  33.09 60.11 180 bottom
C1644  5.6p/50V_4  [C0402]  33.07 61.11 180 bottom
C1645  5.6p/50V_4  [C0402]  23.03 60.89 0 bottom
C1646  5.6p/50V_4  [C0402]  24.9 60.78 0 bottom
C1647  5.6p/50V_4  [C0402]  27.11 57.43 90 bottom
C1648  5.6p/50V_4  [C0402]  32.57 47.52 90 bottom
C1649  1u/25V_4  [C0402]  22.38 61.93 180 bottom
C1650  4.7u/6.3V_4  [C0402_2]  28.12 65.94 270 bottom
C1651  1u/25V_4  [C0402]  33.15 64.33 180 bottom
C1652  0.1u/16V_4  [C0402]  29.26 65.94 90 bottom
C1653  0.1u/16V_4  [C0402]  30.28 65.94 90 bottom
C1687  *HDMI_R_P4@0.1u/16V_4  [C0402]  27.73 145.28 180 top
C1688  HDMI_R_P4@0.1u/16V_4  [C0402]  18.08 139.11 0 top
C1689  HDMI_R_P4@0.1u/16V_4  [C0402]  18.08 138.1 0 top
C1690  *HDMI_R_P4@0.1u/16V_4  [C0402]  27.73 144.32 180 top
C1691  HDMI_R_P4@0.1u/16V_4  [C0402]  27.73 146.26 180 top
C1692  *HDMI_R_P4@0.1u/16V_4  [C0402]  25.58 137.03 90 top
C1693  HDMI_R_P4@0.1u/16V_4  [C0402]  26.56 137.04 90 top
C2321  0.1u/16V_4  [C0402]  84.77 109.76 90 top
C2335  0.1u/16V_4  [C0402]  90.63 105.93 270 top
C2336  *1000p/25V_2  [C0201]  87.2 107.9 90 top
C2337  *1000p/25V_2  [C0201]  87.2 106.22 90 top
C2374  180p/50V_4  [C0402]  148.97 101.57 0 top
C2542  1000p/50V_4  [C0402]  128.34 138.54 90 bottom
C2609  0.1u/16V_2  [C0201]  194.24 104.42 0 bottom
C2611  *0.1u/16V_2  [C0201]  193.98 103.4 270 bottom
C2612  *0.1u/16V_2  [C0201]  194.75 103.4 270 bottom
C2616  *SSD@0.1u/16V_2  [C0201]  13.5 69.98 90 bottom
C6550  0.22u/10V_2  [C0201]  129.82 131.64 0 bottom
C6551  0.22u/10V_2  [C0201]  126.77 130.96 0 bottom
C6552  0.22u/10V_2  [C0201]  129.82 132.38 0 bottom
C6553  0.22u/10V_2  [C0201]  126.77 130.22 0 bottom
C6554  EV@0.22u/10V_4  [C0402]  129.35 210.28 90 top
C6555  EV@0.22u/10V_4  [C0402]  129.42 208.39 90 top
C6556  EV@0.22u/10V_4  [C0402]  128.33 210.28 90 top
C6557  EV@0.22u/10V_4  [C0402]  130.44 208.39 90 top
C6560  *220p/50V_4  [C0402]  15.78 129.9 90 bottom
C6562  *10p/50V_4  [C0402]  146 104.77 180 top
C6563  180p/50V_4  [C0402]  151.18 111.27 180 top
C6564  10u/6.3V_6  [C0603]  171.91 95.45 0 top
C6565  0.1u/10V_2  [C0201]  169.47 107.72 270 top
C6566  0.1u/16V_4  [C0402]  170.26 101.5 270 top
C6568  180p/50V_4  [C0402]  167.74 96.19 180 top
C6569  0.1u/10V_2  [C0201]  170.23 107.72 270 top
C6570  0.1u/10V_2  [C0201]  170.08 95.45 0 top
C6571  1u/6.3V_4  [C0402]  145.98 103.78 180 top
C6572  180p/50V_4  [C0402]  159.92 115.04 270 top
C6573  0.1u/10V_2  [C0201]  151.64 112.36 90 top
C6574  0.1u/10V_2  [C0201]  154 113.05 90 top
C6575  0.1u/10V_2  [C0201]  159.46 112.65 0 top
C6577  0.1u/10V_2  [C0201]  148.44 98.7 270 top
C6578  0.1u/10V_2  [C0201]  149.2 98.7 270 top
C6580  180p/50V_4  [C0402]  167.97 112.54 0 top
C6586  HDD_R@0.01u/10V_2  [C0201]  232.06 120.27 90 top
C6587  HDD_R@0.01u/10V_2  [C0201]  231.3 120.27 90 top
C6588  HDD_R@0.01u/10V_2  [C0201]  230.41 120.27 90 top
C6589  HDD_R@0.01u/10V_2  [C0201]  229.64 120.27 90 top
C6594  HDD_R@0.01u/10V_2  [C0201]  230.5 111.72 90 top
C6595  HDD_R@0.01u/10V_2  [C0201]  229.77 111.72 90 top
C6596  HDD_R@0.01u/10V_2  [C0201]  229.01 111.72 90 top
C6597  HDD_R@0.01u/10V_2  [C0201]  228.27 111.72 90 top
C6598  HDD_R@0.1u/10V_2  [C0201]  233 118.13 90 top
C6599  HDD_R@0.1u/10V_2  [C0201]  233.76 118.13 90 top
C6600  HDD_R@0.1u/10V_2  [C0201]  225.86 112.8 270 top
C6601  HDD_R@0.1u/10V_2  [C0201]  232.24 118.13 90 top
C6602  HDD_R@0.1u/10V_2  [C0201]  226.62 112.8 270 top
C6607  HDD_R@10u/6.3V_4  [C0402_2]  224.84 112.67 90 top
C6609  *0.1U/16V_2  [C0201]  114.31 108.64 180 bottom
C6610  0.1u/16V_4  [C0402]  149.08 102.99 0 top
C6612  0.1u/16V_2  [C0201]  120.58 124.1 180 top
C6613  0.1u/16V_2  [C0201]  124.49 117.65 90 top
C6614  0.1u/16V_2  [C0201]  118.68 116.38 270 top
C6615  0.1u/10V_2  [C0201]  208.79 97.34 180 top
C6616  180p/50V_4  [C0402]  66.48 186.33 270 top
C6618  0.1u/6.3V_2  [C0201]  129.47 159.15 270 bottom
C6619  0.1u/6.3V_2  [C0201]  126.15 143.84 90 bottom
C6620  0.1u/6.3V_2  [C0201]  128.68 123.86 90 top
C6622  0.1u/6.3V_2  [C0201]  128.18 117.01 180 bottom
C6623  0.1u/6.3V_2  [C0201]  113.18 135.71 90 top
C6626  *0.1u/16V_2  [C0201]  102.61 111.23 270 top
C20000  0.1u/16V_4  [C0402]  25.87 166.68 180 top
C20001  180p/50V_4  [C0402]  65.46 186.33 270 top
C20002  180p/50V_4  [C0402]  67.49 186.33 270 top
C20003  *HDMI_CRT_P2@2p/50V_4  [C0402]  13.26 160.17 0 top
C20004  *HDMI_CRT_P2@10p/50V_4  [C0402]  14.02 157.38 180 top
C20005  *HDMI_CRT_P2@220p/50V_4  [C0402]  11.01 158.85 0 bottom
C20006  *HDMI_CRT_P2@10p/50V_4  [C0402]  13.26 161.31 0 top
C20008  *HDMI_CRT_P2@2p/50V_4  [C0402]  13.26 159.03 0 top
C20009  HDMI_CRT_P2@0.22u/10V_2  [C0201]  11.04 157.85 0 bottom
C20010  *HDMI_CRT_P2@2.2u/6.3V_4  [C0402]  35.52 148.51 270 top
C20011  HDMI_CRT_P2@0.1u/16V_4  [C0402]  29.26 148.1 270 top
C20012  HDMI_CRT_P2@0.1u/16V_4  [C0402]  26.02 153.92 0 top
C20013  HDMI_CRT_P2@0.1u/16V_4  [C0402]  25.71 156.61 180 top
C20014  HDMI_CRT_P2@0.1u/16V_4  [C0402]  35.19 151.24 0 top
C20015  HDMI_CRT_P2@0.1u/16V_4  [C0402]  35.19 150.23 0 top
C20016  HDMI_CRT_P2@0.1u/16V_4  [C0402]  35.19 153.28 0 top
C20017  HDMI_CRT_P2@0.1u/16V_4  [C0402]  35.19 154.29 0 top
C20018  HDMI_CRT_P2@0.1u/16V_4  [C0402]  34.85 155.27 0 top
C20019  HDMI_CRT_P2@0.1u/16V_4  [C0402]  34.85 156.29 0 top
C20020  HDMI_CRT_P2@0.1u/16V_4  [C0402]  35.19 152.26 0 top
C20021  HDMI_CRT_P2@0.1u/16V_4  [C0402]  25.97 149.92 90 top
C20022  HDMI_CRT_P2@2.2u/6.3V_4  [C0402]  26.98 149.89 90 top
C20023  *HDMI_CRT_P2@0.1u/16V_4  [C0402]  34.5 148.51 270 top
C20039  SM@47p/50V_4  [C0402]  223.7 92.99 180 top
C20040  SM@1u/25V_4  [C0402]  210.5 95.71 0 top
C20041  SM@0.1u/16V_4  [C0402]  223.7 98.07 180 top
C20042  SM@1u/25V_4  [C0402]  223.7 99.08 180 top
C20043  SM@0.1u/16V_4  [C0402]  210.49 97.94 0 top
C20044  SM@0.1u/16V_4  [C0402]  223.7 101.11 180 top
C20045  SM@1u/25V_4  [C0402]  223.7 100.1 0 top
C20046  SM@0.1u/16V_4  [C0402]  210.49 99.97 0 top
C20047  SM@1u/25V_4  [C0402]  210.49 98.96 180 top
C20048  SM@0.1u/16V_4  [C0402]  220.78 102.89 270 top
C20049  SM@1u/25V_4  [C0402]  221.8 102.89 90 top
C20050  SM@1u/25V_4  [C0402]  215.48 101.88 180 top
C20051  SM@82p/50V_4  [C0402]  215.48 102.89 0 top
C20053  *SM@47p/50V_4  [C0402]  226.03 94.81 180 top
C20055  0.1u/16V_2  [C0201]  18.69 64.14 270 top
C20056  0.1u/16V_2  [C0201]  21.18 64.21 270 top
C20057  0.1u/16V_2  [C0201]  20.42 64.21 270 top
C20058  1u/25V_4  [C0402]  22.51 63.53 0 top
C20059  1u/25V_4  [C0402]  14.2 65.41 0 top
C20060  1u/25V_4  [C0402]  21.94 62.16 270 top
C20061  0.1u/16V_2  [C0201]  21.77 69.49 180 bottom
C20062  0.1u/16V_2  [C0201]  16.12 72.49 90 top
C20063  0.1u/16V_2  [C0201]  14.52 66.26 180 top
C20064  2.2u/10V_4  [C0402]  23.82 64.52 180 top
C20065  0.1u/16V_2  [C0201]  17.69 72.76 270 top
C20066  0.1u/16V_2  [C0201]  22.08 73.8 270 top
C20067  0.1u/16V_2  [C0201]  21.32 73.8 270 top
